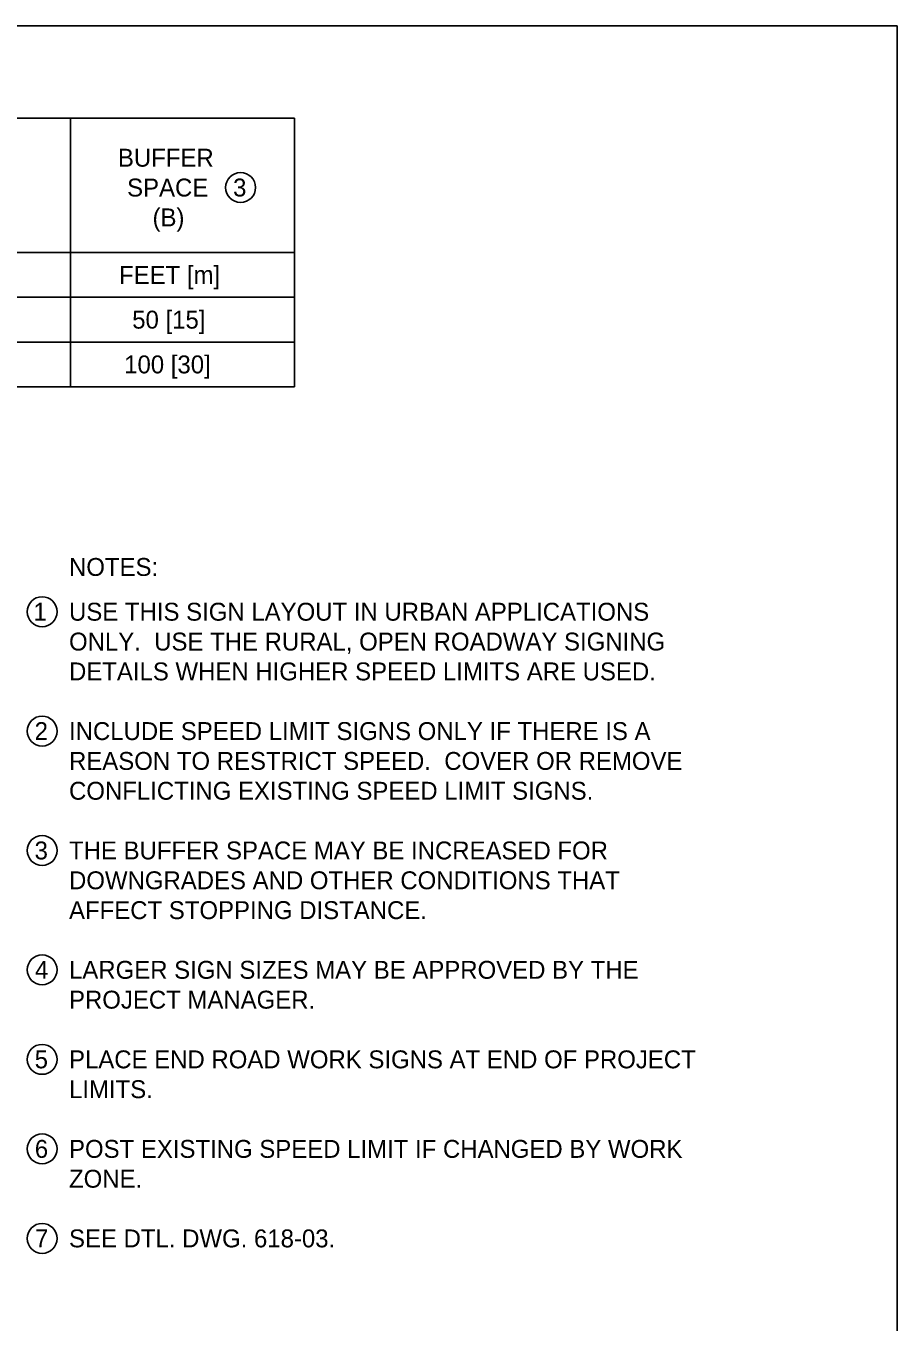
# Model space of a CAD drawing. Extents: x 49991.4 to 50021, y 49987.6 to 50011.4.
# Drawn here: x 50005.696 to 50008.615, y 50006.919 to 50011.263 of the extents above; entities that cross this region are included whole.
import ezdxf

# ---------------------------------------------------------------- set-up
doc = ezdxf.new("R2010")
doc.units = 0
doc.layers.add('Level 1', color=7, linetype='Continuous')
doc.layers.add('Level 2', color=7, linetype='Continuous')

msp = doc.modelspace()

# ---------------------------------------------------------------- linework, layer by layer
at = {"layer": 'Level 1'}
msp.add_lwpolyline([(50008.6146, 50011.2628), (50000.3356, 50011.2628), (50000.3356, 50000.0624), (50008.6146, 50000.0624)], close=True, dxfattribs=at)
at = {"layer": 'Level 2'}
for p, q in [((50002.6653, 50010.9535), (50006.5953, 50010.9535)), ((50005.8453, 50010.9535), (50005.8453, 50010.0535)), ((50006.5953, 50010.9535), (50006.5953, 50010.0535)), ((50002.6653, 50010.5035), (50006.5953, 50010.5035)), ((50002.6653, 50010.3535), (50006.5953, 50010.3535)), ((50002.6653, 50010.2035), (50006.5953, 50010.2035)), ((50002.6653, 50010.0535), (50006.5953, 50010.0535))]:
    msp.add_line(p, q, dxfattribs=at)
for centre in [(50006.4153, 50010.7213), (50005.7503, 50009.2998), (50005.7503, 50008.8998), (50005.7503, 50008.4998), (50005.7503, 50008.0998), (50005.7503, 50007.7998), (50005.7503, 50007.4998), (50005.7503, 50007.1998)]:
    msp.add_circle(centre, 0.0501, dxfattribs=at)

# ---------------------------------------------------------------- texts
for s, p in [('BUFFER', (50006.0042, 50010.7912)), ('SPACE', (50006.035, 50010.6912)), ('3', (50006.3901, 50010.6913)), ('(B)', (50006.1202, 50010.5912)), ('FEET [m]', (50006.008, 50010.3985)), ('50 [15]', (50006.0521, 50010.2485)), ('100 [30]', (50006.0252, 50010.0985)), ('NOTES:', (50005.8404, 50009.4198)), ('1', (50005.7211, 50009.2699)), ('USE THIS SIGN LAYOUT IN URBAN APPLICATIONS', (50005.8404, 50009.2698)), ('ONLY.  USE THE RURAL, OPEN ROADWAY SIGNING', (50005.8404, 50009.1698)), ('DETAILS WHEN HIGHER SPEED LIMITS ARE USED.', (50005.8404, 50009.0698)), ('2', (50005.7252, 50008.8698)), ('INCLUDE SPEED LIMIT SIGNS ONLY IF THERE IS A', (50005.8404, 50008.8698)), ('REASON TO RESTRICT SPEED.  COVER OR REMOVE ', (50005.8404, 50008.7698)), ('CONFLICTING EXISTING SPEED LIMIT SIGNS.', (50005.8404, 50008.6698)), ('3', (50005.7251, 50008.4698)), ('THE BUFFER SPACE MAY BE INCREASED FOR', (50005.8404, 50008.4698)), ('DOWNGRADES AND OTHER CONDITIONS THAT', (50005.8404, 50008.3698)), ('AFFECT STOPPING DISTANCE. ', (50005.8404, 50008.2698)), ('4', (50005.7264, 50008.0698)), ('LARGER SIGN SIZES MAY BE APPROVED BY THE', (50005.8404, 50008.0698)), ('PROJECT MANAGER.', (50005.8404, 50007.9698)), ('5', (50005.7254, 50007.7698)), ('PLACE END ROAD WORK SIGNS AT END OF PROJECT', (50005.8404, 50007.7698)), ('LIMITS.', (50005.8404, 50007.6698)), ('6', (50005.7258, 50007.4698)), ('POST EXISTING SPEED LIMIT IF CHANGED BY WORK', (50005.8404, 50007.4698)), ('ZONE.', (50005.8404, 50007.3698)), ('7', (50005.7265, 50007.1698)), ('SEE DTL. DWG. 618-03.', (50005.8404, 50007.1698))]:
    msp.add_text(s, height=0.06, dxfattribs=at).set_placement(p)

doc.saveas('drawing.dxf')
